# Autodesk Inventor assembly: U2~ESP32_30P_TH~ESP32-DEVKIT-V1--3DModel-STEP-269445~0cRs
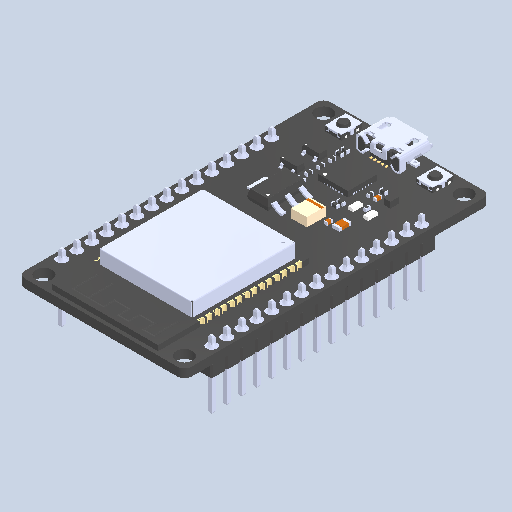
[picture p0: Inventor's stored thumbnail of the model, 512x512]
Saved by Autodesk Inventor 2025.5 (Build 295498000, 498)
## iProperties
Created: 2026-10
Part Number: U2~ESP32_30P_TH~ESP32-DEVKIT-V1--3DModel-STEP-269445~0cRs
Document SubType Name: Assembly
Designer: Luis M
Author: Luis M
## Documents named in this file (2)
- C:\Users\Luis M\Downloads\3D_PCB1_2026-10-28\U2~ESP32_30P_TH~ESP32-DEVKIT-V1--3DModel-STEP-269445~0cRs.iam
- C:\Users\Luis M\Downloads\3D_PCB1_2026-10-28\ESP32_30P_TH~ESP32-DEVKIT-V1--3DModel-STEP-269445~PL2L.ipt
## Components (1 placed, 1 different names)
1. U2->0
